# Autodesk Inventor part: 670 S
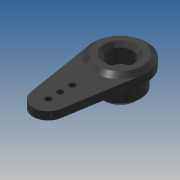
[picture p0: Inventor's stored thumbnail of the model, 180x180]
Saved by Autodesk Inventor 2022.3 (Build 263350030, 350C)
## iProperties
Created: 2021-08
Part Number: 670 S
Material: Nylon 6/6
Document SubType Name: Modeling
Designer: dotwibo2
Mass: 0.28903 g
Surface Area: 4.66998 cm^2
Volume: 0.255779 cm^3
Density: 1.13 g/cm^3
Appearance: Dark Gray
Description: SUPER STRENGTH LONG SERVO SMALL ARM
Vendor: DUBRO
UOFM: EACH
MAKE_OR_BUY: REF
PURCH_QTY: 0
BOM_MATL: -
Note: INCLUDED IN SET
Vendor Part No: 670 S
Alt_PN: DUBRO 670 S
Author: dotwibo2
Title: SUPER STRENGTH LONG SERVO SMALL ARM
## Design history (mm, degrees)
sketch "Sketch1"
  geometry: L1 (0, -7.52)-(0, 4.8) reference; L2 (1.65, -1.71)-(1.65, -2.76); L3 (1.65, -2.76)-(2.925, -2.76); L4 (2.925, -2.76)-(2.925, -5.76); L5 (2.925, -5.76)-(4.25, -5.76); L6 (5.5, -4.51)-(5.5, 0); L7 (5.5, 0)-(7.055, 0); L8 (7.055, 0)-(7.055, 2.1); L9 (7.055, 2.1)-(5.8, 3.04); L10 (5.8, 3.04)-(3.25, 3.04); L11 (-1.411, 0)-(8.466, 0) reference; L12 (1.65, -1.71)-(3.25, -1.71); L13 (3.25, -1.71)-(3.25, 3.04); L14 (5.5, -4.51)-(4.25, -5.76); 1 further point
  constraints: 25 end point, 5 horizontal, 5 vertical, 1 collinear
  dimensions: "d1" = 5.85 diameter of L4 L1; "d2" = 3.3 diameter of L2 L1; "d3" = 8.8 distance between parallel lines of L5 L10; "d7" = 11 diameter of L6 L1; "d9" = 5.76 distance between parallel lines of L7 L5; "d10" = 14.11 diameter of L8 L1; "d20" = 3 distance between parallel lines of L5 L3; "d48" = 6.5 diameter of L13 L1; "d49" = 4.75 distance between parallel lines of L10 L12; "d52" = 2.1 distance of L7.end L8.end; "d53" = 45 deg angle of L6 L14; "d54" = 8.5 diameter of L5.end L1; "d60" = 11.6 diameter of L9.end L1; "d66" = 0.94 vertical distance of L8.end L9.end (derived)
revolve "Revolution1" sketch "Sketch1" stored, may be unused: angle "d11" = 90 deg
sketch "Sketch3"
  geometry: L1 (-6.964, 1.131)-(-3.948, 19.691); L2 (3.948, 19.691)-(6.964, 1.131); L3 (9.877, 0)-(-9.877, 0) reference; L4 (0, -14.346)-(0, 36.691) reference; C1 r 7.055 at (0, 0) reference; A1 r 4 centre (0, 19.05) between (3.948, 19.691) and (-3.948, 19.691); A2 r 7.055 centre (0, 0) between (6.964, 1.131) and (-6.964, 1.131); 4 further points
  constraints: 4 end point, 4 point on circle, 3 tangent, 2 centre point, 2 coincident, 2 point on line, 1 concentric, 1 other
  dimensions: "d21" = 19.05 distance from line of L3 A1.centre; "d22" = 8 diameter of A1; "d29" = 3.175 distance of point (0, 19.05) point (0, 15.875); "d30" = 3.175 distance of point (0, 12.7) point (0, 15.875) (= d29)
extrude "Extrusion2" join sketch "Sketch3" distance "d27" = 2.1; taper "d28" = 0 deg
hole "Hole1" sketch "Sketch3" diameter "d31" = 1.5875; stored, may be unused: countersink angle "d35" = 90 deg, drill point angle "d37" = 118 deg; dims "d32" = 4, "d33" = 4, "d34" = 2, "d36" = 5
chamfer "Chamfer1" distance "d67" = 1; stored, may be unused: second distance "d68" = 2, angle "d69" = 45 deg
body "Solid1"
